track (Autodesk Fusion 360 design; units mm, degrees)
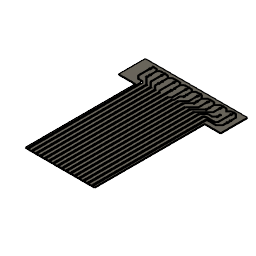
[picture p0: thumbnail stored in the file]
base_feature "Base Feature"
offset_faces "OffsetFaces1" distance -0.8
extrude "Extrude1" cut of existing geometry blind -0.6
